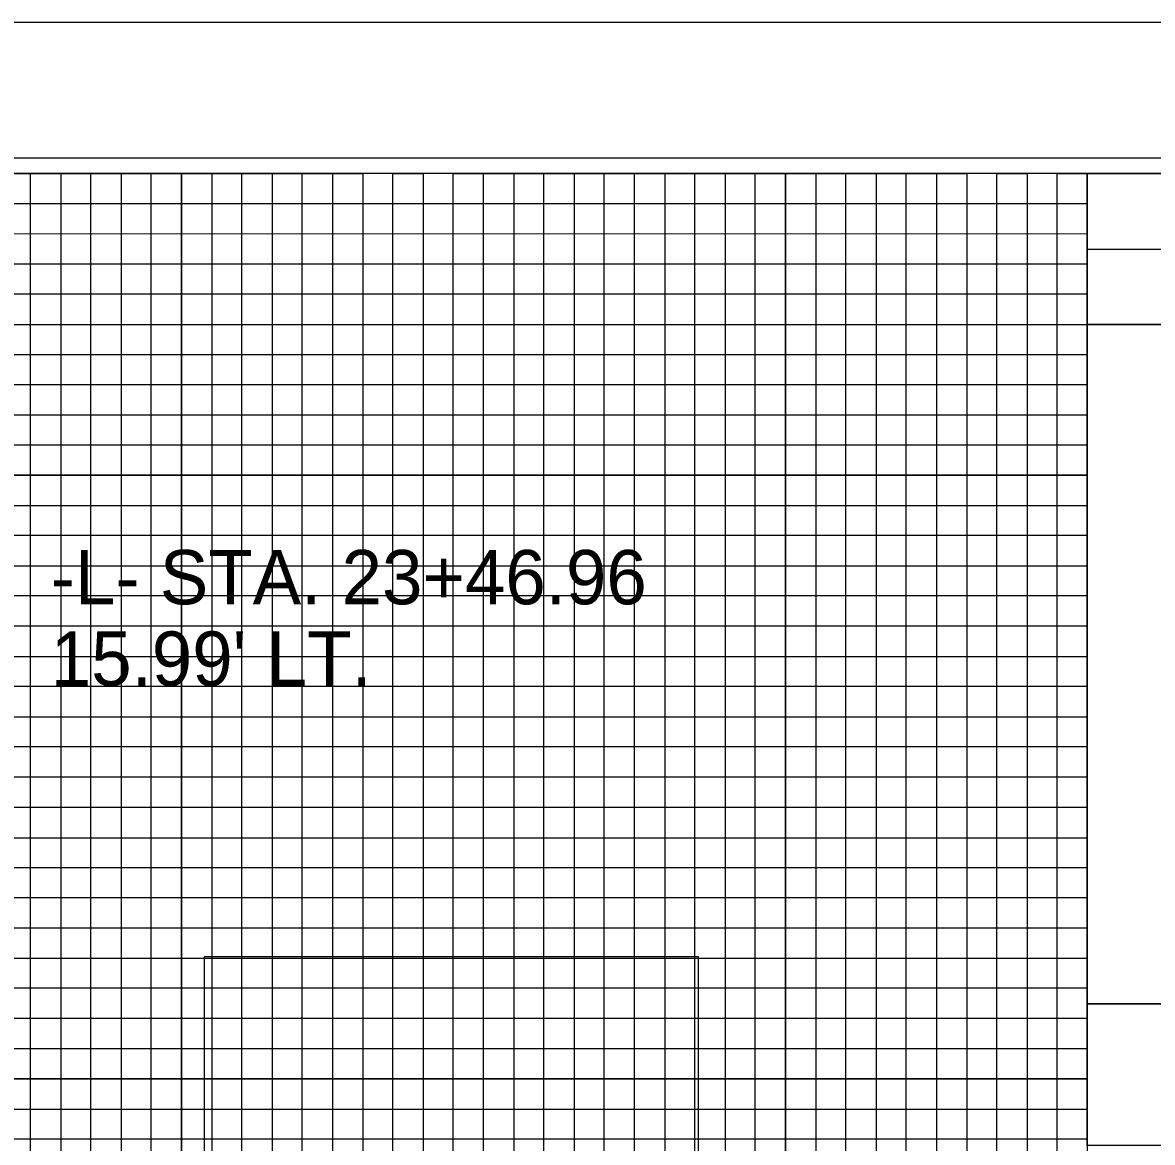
# Model space of a CAD drawing. Extents: x 557032 to 558840, y 515971 to 517218.
# Drawn here: x 558323.1 to 558510.2, y 517032.6 to 517218.2 of the extents above; entities that cross this region are included whole.
import ezdxf

# ---------------------------------------------------------------- set-up
doc = ezdxf.new("R2010")
doc.units = 0
for name, color, linetype in [('Prop Vertical Profile Grade Label', 7, 'Continuous'), ('Prop VPI Label', 7, 'Continuous'), ('Scratch_Level_5', 7, 'Continuous'), ('Sheet Cutting Line CELL', 7, 'Continuous'), ('Sheet DOT Grid CELL', 7, 'Continuous'), ('Sheet Plot Border Inside CELL', 7, 'Continuous'), ('Sheet Plot Border Outside CELL', 7, 'Continuous'), ('Sheet Profile CELL', 7, 'Continuous'), ('Sheet Profile Grid Major CELL', 7, 'Continuous'), ('Sheet Profile Grid Middle CELL', 7, 'Continuous'), ('Sheet Profile Grid Minor CELL', 7, 'Continuous'), ('Sheet Sticker Exception Certification CELL', 7, 'Continuous')]:
    doc.layers.add(name, color=color, linetype=linetype)

msp = doc.modelspace()

# ---------------------------------------------------------------- linework, layer by layer
at = {"layer": 'Prop Vertical Profile Grade Label'}
msp.add_lwpolyline([(558353.25, 517063.44), (558435.01, 517063.44), (558435.01, 517009.9), (558353.25, 517009.9)], close=True, dxfattribs=at)
at = {"layer": 'Scratch_Level_5'}
msp.add_lwpolyline([(558499.45, 517193.17), (558099.45, 517193.17), (558099.45, 516693.17), (558649.45, 516693.17), (558649.45, 517032.12), (558499.45, 517032.12)], close=True, dxfattribs=at)
at = {"layer": 'Sheet Cutting Line CELL'}
msp.add_line((558716.45, 517218.17), (557032.45, 517218.17), dxfattribs=at)
at = {"layer": 'Sheet DOT Grid CELL'}
for p, q in [((558349.45, 516693.17), (558349.45, 517193.17)), ((558399.45, 516693.17), (558399.45, 517193.17)), ((558449.45, 516693.17), (558449.45, 517193.17)), ((558499.4, 517143.17), (557199.45, 517143.17)), ((558499.4, 517093.17), (557199.45, 517093.17)), ((558499.45, 516693.17), (558499.45, 517055.62)), ((558499.45, 517043.17), (557199.45, 517043.17))]:
    msp.add_line(p, q, dxfattribs=at)
at = {"layer": 'Sheet Plot Border Inside CELL'}
msp.add_lwpolyline([(557045.45, 516140.62), (558711.95, 516140.62), (558711.95, 517195.72), (557045.45, 517195.72)], close=True, dxfattribs=at)
at = {"layer": 'Sheet Plot Border Outside CELL'}
msp.add_lwpolyline([(557032.45, 516118.17), (558716.45, 516118.17), (558716.45, 517218.17), (557032.45, 517218.17)], close=True, dxfattribs=at)
at = {"layer": 'Sheet Profile CELL'}
msp.add_line((558499.4, 517180.62), (558699.45, 517180.62), dxfattribs=at)
for points in [[(558699.45, 517193.17), (557199.45, 517193.17), (557199.45, 516143.17), (558699.45, 516143.17)], [(558499.4, 517193.17), (558699.45, 517193.17), (558699.45, 517168.12), (558499.4, 517168.12)], [(558499.4, 517168.12), (558599.45, 517168.12), (558599.45, 517055.62), (558499.4, 517055.62)]]:
    msp.add_lwpolyline(points, close=True, dxfattribs=at)
at = {"layer": 'Sheet Profile Grid Major CELL'}
for points in [[(557999.45, 517193.17), (558049.45, 517193.17), (558049.45, 516842.99), (558099.45, 516842.99), (558099.45, 517193.17), (558149.45, 517193.17), (558149.45, 516693.17), (558199.45, 516693.17), (558199.45, 517193.17), (558249.45, 517193.17), (558249.45, 516693.17), (558299.45, 516693.17), (558299.45, 517193.17), (558349.45, 517193.17), (558349.45, 516693.17), (558399.45, 516693.17), (558399.45, 517193.17), (558449.45, 517193.17), (558449.45, 516693.17), (558499.45, 516693.17), (558499.45, 517193.17), (558525.75, 517193.17)], [(557199.45, 517143.17), (558499.45, 517143.17)], [(558499.45, 517093.17), (557199.45, 517093.17), (557199.45, 517043.17), (558499.45, 517043.17)]]:
    msp.add_lwpolyline(points, dxfattribs=at)
at = {"layer": 'Sheet Profile Grid Middle CELL'}
msp.add_line((557199.45, 517168.17), (558499.4, 517168.17), dxfattribs=at)
for points in [[(558024.45, 517193.17), (558074.45, 517193.17), (558074.45, 516693.17), (558124.45, 516693.17), (558124.45, 517193.17), (558174.45, 517193.17), (558174.45, 516693.17), (558224.45, 516693.17), (558224.45, 517193.17), (558274.45, 517193.17), (558274.45, 516693.17), (558324.45, 516693.17), (558324.45, 517193.17), (558374.45, 517193.17), (558374.45, 516693.17), (558424.45, 516693.17), (558424.45, 517193.17), (558474.45, 517193.17), (558474.45, 516693.17), (558524.45, 516693.17), (558524.45, 517032.12)], [(558499.45, 517118.17), (557199.45, 517118.17), (557199.45, 517068.17), (558499.45, 517068.17)]]:
    msp.add_lwpolyline(points, dxfattribs=at)
at = {"layer": 'Sheet Profile Grid Minor CELL'}
for p, q in [((557249.45, 517188.17), (558499.45, 517188.17)), ((558499.45, 517183.17), (557249.45, 517182.82)), ((557249.45, 517178.17), (558499.45, 517178.17)), ((558499.4, 517058.17), (557249.45, 517058.17)), ((558499.45, 517053.17), (557249.45, 517053.17)), ((558499.45, 517048.17), (557249.45, 517048.17)), ((557249.45, 517038.17), (558499.45, 517038.17)), ((558499.45, 517033.17), (557249.45, 517033.17))]:
    msp.add_line(p, q, dxfattribs=at)
for points in [[(558319.45, 517193.17), (558329.45, 517193.17), (558329.45, 516693.17), (558334.45, 516693.17), (558334.45, 517193.17), (558339.45, 517193.17), (558339.45, 516693.17), (558344.45, 516693.17), (558344.45, 517193.17), (558354.45, 517193.17), (558354.45, 516693.17), (558359.45, 516693.17), (558359.45, 517193.17), (558364.45, 517193.17), (558364.45, 516693.17), (558369.45, 516693.17), (558369.45, 517193.17), (558379.45, 517193.17), (558379.45, 516693.17), (558384.45, 516693.17), (558384.45, 517193.17), (558389.45, 517193.17), (558389.45, 516693.17)], [(558394.45, 516693.17), (558394.45, 517193.17), (558404.45, 517193.17), (558404.45, 516693.17)], [(558409.45, 516693.17), (558409.45, 517193.17), (558414.45, 517193.17), (558414.45, 516693.17)], [(558419.45, 516693.17), (558419.45, 517193.17), (558429.45, 517193.17), (558429.45, 516693.17)], [(558434.45, 516693.17), (558434.45, 517193.17), (558439.45, 517193.17), (558439.45, 516693.17)], [(558444.45, 516693.17), (558444.45, 517193.17), (558454.45, 517193.17), (558454.45, 516693.17)], [(558459.45, 516693.17), (558459.45, 517193.17), (558464.45, 517193.17), (558464.45, 516693.17)], [(558469.45, 516693.17), (558469.45, 517193.17), (558479.45, 517193.17), (558479.45, 516693.17)], [(558484.45, 516693.17), (558484.45, 517193.17), (558489.45, 517193.17), (558489.45, 516693.17)], [(558494.45, 516693.17), (558494.45, 517193.17), (558504.45, 517193.17)], [(558499.45, 517173.17), (557249.45, 517173.17), (557249.45, 517163.17), (558499.45, 517163.17)], [(558499.4, 517158.17), (557249.45, 517158.17), (557249.45, 517153.17), (558499.45, 517153.17)], [(558499.45, 517148.17), (557249.45, 517148.17), (557249.45, 517138.17), (558499.45, 517138.17)], [(558499.45, 517133.17), (557249.45, 517133.17), (557249.45, 517128.17), (558499.45, 517128.17)], [(558499.45, 517123.17), (557249.45, 517123.17), (557249.45, 517113.17), (558499.45, 517113.17)], [(558499.45, 517108.17), (557249.45, 517108.17), (557249.45, 517103.17), (558499.45, 517103.17)], [(558499.45, 517098.17), (557249.45, 517098.17), (557249.45, 517088.17), (558499.45, 517088.17)], [(558499.45, 517083.07), (557249.55, 517083.07), (557249.55, 517078.17), (558499.45, 517078.17)], [(558499.45, 517073.17), (557249.45, 517073.17), (557249.45, 517063.17), (558499.45, 517063.17)]]:
    msp.add_lwpolyline(points, dxfattribs=at)
at = {"layer": 'Sheet Sticker Exception Certification CELL'}
for p, q in [((558499.4, 517032.12), (558499.4, 517055.62)), ((558499.4, 517055.62), (558699.44, 517055.62)), ((558499.4, 517032.12), (558499.4, 517055.62)), ((558499.4, 517055.62), (558699.44, 517055.62))]:
    msp.add_line(p, q, dxfattribs=at)

# ---------------------------------------------------------------- texts
at = {"layer": 'Prop VPI Label'}
for s, p in [('-L- STA. 23+46.96', (558327.81, 517121.79)), ("15.99' LT.", (558327.81, 517108.29))]:
    msp.add_text(s, height=9, dxfattribs=at).set_placement(p)

doc.saveas('drawing.dxf')
